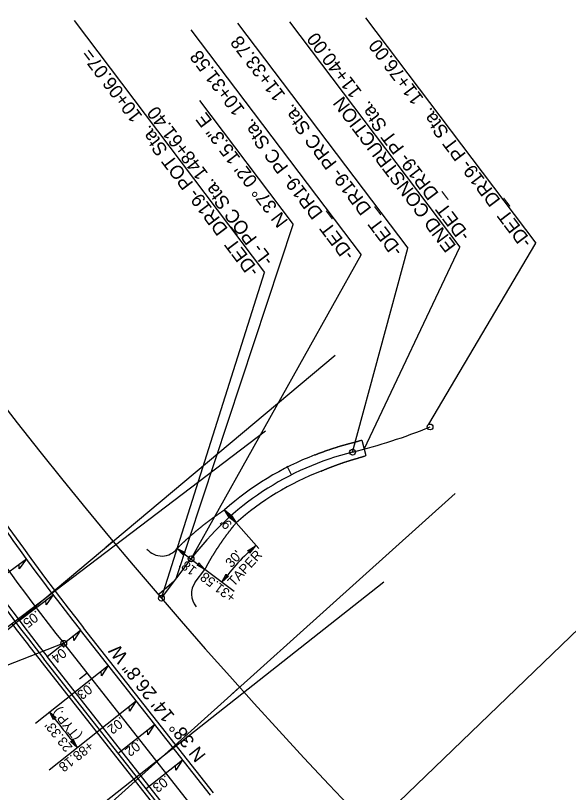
# Model space of a CAD drawing. Extents: x 473658 to 481584, y 489119 to 506230.
# Drawn here: x 476370.9 to 476657.4, y 500835 to 501237.1 of the extents above; entities that cross this region are included whole.
import ezdxf

# ---------------------------------------------------------------- set-up
doc = ezdxf.new("R2010")
doc.units = 0
for name, color, linetype in [('Exist Horizontal Alignment', 7, 'Continuous'), ('Prop Dimension', 7, 'Continuous'), ('Prop EOT', 7, 'Continuous'), ('Prop Guardrail', 7, 'Continuous'), ('Prop Horizontal Alignment', 7, 'Continuous'), ('Prop Horizontal Alignment Direction Label', 7, 'Continuous'), ('Prop Horizontal Alignment Station Label', 7, 'Continuous'), ('Prop Horizontal Alignment Tick Small', 7, 'Continuous'), ('Prop Paved Shoulder', 7, 'Continuous'), ('Prop Superelevation  Arrow CELL', 7, 'Continuous'), ('Prop Superelevation Label', 7, 'Continuous'), ('Scratch_Level_6', 7, 'Continuous'), ('Scratch_Level_9', 7, 'Continuous'), ('Sheet Plan And Profile CELL', 7, 'Continuous'), ('Sheet Profile Grid Major CELL', 7, 'Continuous')]:
    doc.layers.add(name, color=color, linetype=linetype)

msp = doc.modelspace()

# ---------------------------------------------------------------- linework, layer by layer
at = {"layer": 'Exist Horizontal Alignment'}
for points in [[(476481.64, 500977.41), (476479.24, 500981.29), (476482.84, 500978.43), (476481.86, 500978.33)], [(476482.8, 500978.43), (476485.2, 500974.55), (476481.61, 500977.41), (476482.59, 500977.51)], [(476491.16, 500960.14), (476495.04, 500962.55), (476492.19, 500958.95), (476492.09, 500959.92)], [(476457.83, 500958.02), (476454.7, 500961.35), (476458.79, 500959.27), (476457.85, 500958.97)], [(476465.94, 500953.84), (476469.07, 500950.51), (476464.97, 500952.6), (476465.92, 500952.89)], [(476481.23, 500946.96), (476477.85, 500943.89), (476480, 500947.95), (476480.28, 500947)]]:
    msp.add_lwpolyline(points, close=True, dxfattribs=at)
at = {"layer": 'Prop Dimension'}
for p, q in [((476485.2, 500974.55), (476479.24, 500981.29)), ((476454.7, 500961.35), (476469.07, 500950.51))]:
    msp.add_line(p, q, dxfattribs=at)
at = {"layer": 'Prop EOT'}
for p, q in [((476550.29, 501017.38), (476552.45, 501009.36)), ((476464.04, 500943.84), (476469.07, 500950.51)), ((476471.89, 500833.57), (476404.54, 500919.03)), ((476454.61, 500819.95), (476387.26, 500905.41))]:
    msp.add_line(p, q, dxfattribs=at)
for centre, radius, start, end in [((477416.95, 501716.88), 1289, 209.06204, 218.24077), ((477416.95, 501716.88), 1311, 209.06204, 218.24077), ((476581.62, 500865.58), 154.5, 111.0985, 131.5034), ((476581.62, 500865.58), 145.5, 111.0985, 131.5034), ((476446.74, 500967.4), 10, 219.7156, 322.9624), ((476472.02, 500937.82), 10, 142.9624, 221.5291)]:
    msp.add_arc(centre, radius, start, end, dxfattribs=at)
for points in [[(476526, 501009.72), (476526.33, 501009.85), (476526.65, 501009.98), (476526.98, 501010.11), (476527.3, 501010.24), (476527.62, 501010.36), (476527.95, 501010.49), (476528.27, 501010.61), (476528.6, 501010.73), (476528.93, 501010.86), (476529.25, 501010.98), (476529.58, 501011.1), (476529.9, 501011.22), (476530.23, 501011.34), (476530.56, 501011.46), (476530.88, 501011.58), (476531.21, 501011.7), (476531.54, 501011.82), (476531.87, 501011.93), (476532.2, 501012.05), (476532.53, 501012.16), (476532.85, 501012.28), (476533.18, 501012.39), (476533.51, 501012.5), (476533.84, 501012.61), (476534.17, 501012.73), (476534.5, 501012.84), (476534.83, 501012.95), (476535.16, 501013.06), (476535.5, 501013.16), (476535.83, 501013.27), (476536.16, 501013.38), (476536.49, 501013.48), (476536.82, 501013.59), (476537.15, 501013.69), (476537.49, 501013.8), (476537.82, 501013.9), (476538.15, 501014), (476538.49, 501014.1), (476538.82, 501014.21), (476539.15, 501014.31), (476539.49, 501014.4), (476539.82, 501014.5), (476540.16, 501014.6), (476540.49, 501014.7), (476540.82, 501014.79), (476541.16, 501014.89), (476541.49, 501014.98), (476541.83, 501015.08), (476542.17, 501015.17), (476542.5, 501015.26), (476542.84, 501015.36), (476543.17, 501015.45), (476543.51, 501015.54), (476543.85, 501015.63), (476544.19, 501015.72), (476544.52, 501015.8), (476544.84, 501015.89), (476545.16, 501015.97), (476545.48, 501016.06), (476545.8, 501016.14), (476546.12, 501016.23), (476546.44, 501016.31), (476546.77, 501016.4), (476547.09, 501016.49), (476547.41, 501016.58), (476547.73, 501016.66), (476548.05, 501016.75), (476548.37, 501016.84), (476548.69, 501016.93), (476549.01, 501017.02), (476549.33, 501017.11), (476549.65, 501017.2), (476550.29, 501017.38)], [(476529.24, 501001.33), (476529.55, 501001.46), (476529.85, 501001.59), (476530.15, 501001.72), (476530.45, 501001.85), (476530.75, 501001.97), (476531.06, 501002.1), (476531.36, 501002.23), (476531.66, 501002.35), (476531.97, 501002.48), (476532.27, 501002.6), (476532.57, 501002.72), (476532.88, 501002.85), (476533.18, 501002.97), (476533.49, 501003.09), (476533.79, 501003.21), (476534.1, 501003.33), (476534.4, 501003.45), (476534.71, 501003.57), (476535.02, 501003.69), (476535.32, 501003.81), (476535.63, 501003.92), (476535.94, 501004.04), (476536.25, 501004.16), (476536.55, 501004.27), (476536.86, 501004.38), (476537.17, 501004.5), (476537.48, 501004.61), (476537.79, 501004.72), (476538.1, 501004.83), (476538.41, 501004.94), (476538.72, 501005.05), (476539.03, 501005.16), (476539.34, 501005.27), (476539.65, 501005.38), (476539.96, 501005.49), (476540.27, 501005.59), (476540.58, 501005.7), (476540.9, 501005.8), (476541.21, 501005.91), (476541.52, 501006.01), (476541.83, 501006.12), (476542.15, 501006.22), (476542.46, 501006.32), (476542.77, 501006.42), (476543.09, 501006.52), (476543.4, 501006.62), (476543.71, 501006.72), (476544.03, 501006.82), (476544.34, 501006.92), (476544.66, 501007.01), (476544.97, 501007.11), (476545.29, 501007.2), (476545.61, 501007.3), (476545.92, 501007.39), (476546.24, 501007.49), (476546.56, 501007.58), (476546.89, 501007.68), (476547.22, 501007.77), (476547.54, 501007.87), (476547.87, 501007.96), (476548.2, 501008.06), (476548.53, 501008.16), (476548.86, 501008.26), (476549.18, 501008.36), (476549.51, 501008.46), (476549.84, 501008.55), (476550.17, 501008.65), (476550.49, 501008.75), (476550.82, 501008.85), (476551.15, 501008.95), (476551.47, 501009.06), (476551.8, 501009.16), (476552.45, 501009.36)], [(476454.7, 500961.35), (476455.01, 500961.66), (476455.32, 500961.96), (476455.63, 500962.27), (476455.94, 500962.57), (476456.25, 500962.87), (476456.56, 500963.17), (476456.87, 500963.47), (476457.18, 500963.77), (476457.5, 500964.07), (476457.81, 500964.37), (476458.12, 500964.67), (476458.44, 500964.96), (476458.76, 500965.25), (476459.07, 500965.55), (476459.39, 500965.84), (476459.71, 500966.13), (476460.03, 500966.42), (476460.35, 500966.71), (476460.67, 500967), (476460.99, 500967.29), (476461.31, 500967.57), (476461.63, 500967.86), (476461.96, 500968.14), (476462.28, 500968.43), (476462.6, 500968.71), (476462.93, 500968.99), (476463.26, 500969.27), (476463.58, 500969.55), (476463.91, 500969.83), (476464.24, 500970.11), (476464.56, 500970.38), (476464.89, 500970.66), (476465.22, 500970.93), (476465.55, 500971.2), (476465.88, 500971.48), (476466.22, 500971.75), (476466.55, 500972.02), (476466.88, 500972.29), (476467.21, 500972.56), (476467.55, 500972.82), (476467.88, 500973.09), (476468.22, 500973.35), (476468.55, 500973.62), (476468.89, 500973.88), (476469.23, 500974.14), (476469.56, 500974.4), (476469.9, 500974.66), (476470.24, 500974.92), (476470.58, 500975.18), (476470.92, 500975.44), (476471.26, 500975.69), (476471.6, 500975.95), (476471.94, 500976.2), (476472.28, 500976.46), (476472.63, 500976.71), (476472.97, 500976.96), (476473.31, 500977.21), (476473.66, 500977.46), (476474, 500977.7), (476474.35, 500977.95), (476474.69, 500978.19), (476475.04, 500978.44), (476475.39, 500978.68), (476475.73, 500978.92), (476476.08, 500979.17), (476476.43, 500979.41), (476476.78, 500979.65), (476477.13, 500979.88), (476477.48, 500980.12), (476477.83, 500980.36), (476478.18, 500980.59), (476478.53, 500980.83), (476479.24, 500981.29)], [(476469.07, 500950.51), (476469.25, 500950.85), (476469.43, 500951.19), (476469.62, 500951.53), (476469.8, 500951.87), (476469.99, 500952.21), (476470.17, 500952.55), (476470.36, 500952.89), (476470.55, 500953.23), (476470.74, 500953.56), (476470.93, 500953.9), (476471.12, 500954.24), (476471.31, 500954.57), (476471.51, 500954.91), (476471.7, 500955.25), (476471.9, 500955.58), (476472.09, 500955.92), (476472.29, 500956.25), (476472.49, 500956.59), (476472.69, 500956.92), (476472.89, 500957.25), (476473.09, 500957.59), (476473.3, 500957.92), (476473.5, 500958.25), (476473.7, 500958.58), (476473.91, 500958.91), (476474.12, 500959.24), (476474.33, 500959.57), (476474.53, 500959.9), (476474.74, 500960.23), (476474.95, 500960.56), (476475.17, 500960.89), (476475.38, 500961.22), (476475.59, 500961.55), (476475.81, 500961.87), (476476.02, 500962.2), (476476.24, 500962.53), (476476.46, 500962.85), (476476.68, 500963.18), (476476.9, 500963.5), (476477.12, 500963.83), (476477.34, 500964.15), (476477.56, 500964.47), (476477.79, 500964.8), (476478.01, 500965.12), (476478.24, 500965.44), (476478.46, 500965.76), (476478.69, 500966.08), (476478.92, 500966.4), (476479.15, 500966.72), (476479.38, 500967.04), (476479.61, 500967.36), (476479.84, 500967.68), (476480.08, 500968), (476480.31, 500968.31), (476480.55, 500968.63), (476480.78, 500968.95), (476481.02, 500969.26), (476481.26, 500969.58), (476481.5, 500969.89), (476481.74, 500970.21), (476481.98, 500970.52), (476482.22, 500970.83), (476482.46, 500971.15), (476482.71, 500971.46), (476482.95, 500971.77), (476483.2, 500972.08), (476483.45, 500972.39), (476483.69, 500972.7), (476483.94, 500973.01), (476484.19, 500973.32), (476484.44, 500973.63), (476484.7, 500973.94), (476485.2, 500974.55)]]:
    msp.add_spline(points, degree=3, dxfattribs=at)
at = {"layer": 'Prop Guardrail'}
msp.add_line((476384.12, 500902.94), (476451.47, 500817.48), dxfattribs=at)
msp.add_arc((477416.95, 501716.88), 1315, 217.16826, 218.24077, dxfattribs=at)
at = {"layer": 'Prop Horizontal Alignment'}
for p, q in [((476446.52, 500935.57), (476461.88, 500955.93)), ((476463.25, 500826.76), (476395.9, 500912.22))]:
    msp.add_line(p, q, dxfattribs=at)
for centre, radius, start, end in [((478615.62, 502799.59), 2860, 203.81642, 228.24762), ((477416.95, 501716.88), 1300, 209.06204, 218.24077), ((476473.34, 501302.36), 300, 283.9239, 291.9867), ((476581.62, 500865.58), 150, 103.9239, 142.9624)]:
    msp.add_arc(centre, radius, start, end, dxfattribs=at)
at = {"layer": 'Prop Horizontal Alignment Station Label'}
for p, q in [((476401.25, 501234.59), (476499.97, 501104.18)), ((476485.95, 501233.21), (476574.19, 501116.64)), ((476512.94, 501233.88), (476601.18, 501117.31)), ((476552.22, 501235.94), (476640.46, 501119.38)), ((476461.79, 501229.75), (476550.02, 501113.19)), ((476466.29, 501193.07), (476514.81, 501128.97)), ((476454.2, 500945.75), (476514.81, 501128.97)), ((476585.09, 501025.57), (476640.46, 501119.38)), ((476545.53, 501011.17), (476574.19, 501116.64)), ((476551.54, 501012.73), (476601.18, 501117.31)), ((476461.88, 500955.93), (476550.02, 501113.19)), ((476446.52, 500935.57), (476499.97, 501104.18)), ((476395.9, 500912.22), (476295.9, 500873.14))]:
    msp.add_line(p, q, dxfattribs=at)
for centre in [(476585.65, 501024.18), (476545.53, 501011.17), (476461.88, 500955.93), (476446.51, 500935.57), (476395.9, 500912.22)]:
    msp.add_circle(centre, 1.5, dxfattribs=at)
at = {"layer": 'Prop Horizontal Alignment Tick Small'}
for p, q in [((476513.92, 500999.44), (476511.67, 501003.9)), ((476421.49, 500965.09), (476417.65, 500961.89)), ((476408.04, 500896.81), (476404.12, 500893.72)), ((476486.96, 500889.51), (476483.24, 500886.17))]:
    msp.add_line(p, q, dxfattribs=at)
at = {"layer": 'Prop Paved Shoulder'}
for p, q in [((476473.46, 500834.81), (476406.11, 500920.27)), ((476453.04, 500818.71), (476385.69, 500904.17))]:
    msp.add_line(p, q, dxfattribs=at)
for radius in [1287, 1313]:
    msp.add_arc((477416.95, 501716.88), radius, 209.06204, 218.24077, dxfattribs=at)
at = {"layer": 'Prop Superelevation  Arrow CELL'}
for points in [[(476376.56, 500955.88), (476372.9, 500950.72), (476372.83, 500953.15)], [(476390.39, 500937.33), (476386.82, 500932.11), (476386.7, 500934.53)], [(476404.54, 500919.03), (476401.07, 500913.74), (476400.91, 500916.17)], [(476418.98, 500900.71), (476415.51, 500895.42), (476415.35, 500897.85)], [(476433.42, 500882.39), (476429.95, 500877.1), (476429.79, 500879.52)], [(476390.69, 500872.68), (476388.51, 500876.7), (476391.94, 500873.64), (476390.95, 500873.59)], [(476443.02, 500870.21), (476439.54, 500864.92), (476439.39, 500867.35)], [(476400.75, 500862.37), (476402.93, 500858.36), (476399.5, 500861.42), (476400.49, 500861.46)], [(476457.46, 500851.88), (476453.98, 500846.6), (476453.83, 500849.02)]]:
    msp.add_lwpolyline(points, close=True, dxfattribs=at)
at = {"layer": 'Prop Superelevation Label'}
for p, q in [((476358.8, 500942.89), (476376.56, 500955.88)), ((476372.86, 500924.02), (476390.39, 500937.33)), ((476387.26, 500905.42), (476404.54, 500919.03)), ((476381.25, 500870.97), (476418.98, 500900.71)), ((476388.3, 500846.82), (476433.42, 500882.39)), ((476424.17, 500855.35), (476443.02, 500870.21)), ((476438.61, 500837.03), (476457.46, 500851.88))]:
    msp.add_line(p, q, dxfattribs=at)
msp.add_arc((477329.4, 501601.99), 1187.99, 217.62716, 218.75237, dxfattribs=at)
at = {"layer": 'Scratch_Level_6'}
for p, q in [((476261.46, 500840.89), (476500.52, 501022.13)), ((476326.13, 500758.42), (476561.76, 500944.11))]:
    msp.add_line(p, q, dxfattribs=at)
at = {"layer": 'Scratch_Level_9'}
msp.add_line((476453.17, 500944.39), (476445.36, 500937.68), dxfattribs=at)
at = {"layer": 'Sheet Plan And Profile CELL'}
for p, q in [((476306.41, 500868.88), (476536.56, 501061.31)), ((476375.32, 500789.33), (476598.6, 500989.69)), ((476446.96, 500712.24), (476663.1, 500920.29))]:
    msp.add_line(p, q, dxfattribs=at)
at = {"layer": 'Sheet Profile Grid Major CELL'}
for p, q in [((476496.92, 500961.31), (476485.2, 500974.55)), ((476484.21, 500939.09), (476469.07, 500950.51))]:
    msp.add_line(p, q, dxfattribs=at)
msp.add_arc((476581.62, 500865.58), 130, 131.5034, 142.9624, dxfattribs=at)

# ---------------------------------------------------------------- texts
at = {"layer": 'Prop Dimension'}
for s, rotation, p in [("9'", 131.5034, (476483.5, 500973.89)), ("18'", 142.9624, (476465.23, 500950.88)), ('+31.58', 142.9611, (476485.55, 500937))]:
    msp.add_text(s, height=5, rotation=rotation, dxfattribs=at).set_placement(p)
at = {"layer": 'Prop Horizontal Alignment Direction Label'}
for s, rotation, p in [('N 37%%d 02\' 15.3" E', 127.1236, (476512.45, 501130.76)), ('N 38%%d 14\' 26.8" W', 128.2408, (476469.89, 500854.26))]:
    msp.add_text(s, height=7, rotation=rotation, dxfattribs=at).set_placement(p)
at = {"layer": 'Prop Horizontal Alignment Station Label'}
for s, p in [('-DET_DR19- PT Sta.  11+40.00', (476606.82, 501123.47)), ('-DET_DR19- PRC Sta.  11+33.78', (476571.95, 501115.6)), ('-DET_DR19- PT Sta.  11+76.00', (476638.82, 501120.03)), ('-DET_DR19- POT Sta.  10+06.07=', (476497.59, 501105.08)), ('-DET_DR19- PC Sta.  10+31.58', (476546.85, 501113.46)), ('END CONSTRUCTION', (476599.53, 501117.96)), ('-L- POC Sta. 148+61.40', (476504.88, 501110.59))]:
    msp.add_text(s, height=7, rotation=127.1236, dxfattribs=at).set_placement(p)
at = {"layer": 'Prop Superelevation Label'}
for s, rotation, p in [('.05', 217.2123, (476381.69, 500929.47)), ('.04', 218.2242, (476396.34, 500911.18)), ('.03', 218.2408, (476409.63, 500892.39)), ('(TYP.)', 128.267, (476405.4, 500864.39)), ('.02', 218.2408, (476425.37, 500874.47)), ("23.33'", 128.267, (476400.78, 500858.49)), ('.02', 218.2408, (476434.49, 500862.93)), ('+88.18', 218.267, (476409, 500861.97)), ('.03', 218.2408, (476448.77, 500844.28))]:
    msp.add_text(s, height=5, rotation=rotation, dxfattribs=at).set_placement(p)
at = {"layer": 'Sheet Profile Grid Major CELL'}
for s, p in [("30'", (476482.79, 500951.03)), ('TAPER', (476484, 500941.29))]:
    msp.add_text(s, height=5, rotation=47.3241, dxfattribs=at).set_placement(p)

doc.saveas('drawing.dxf')
